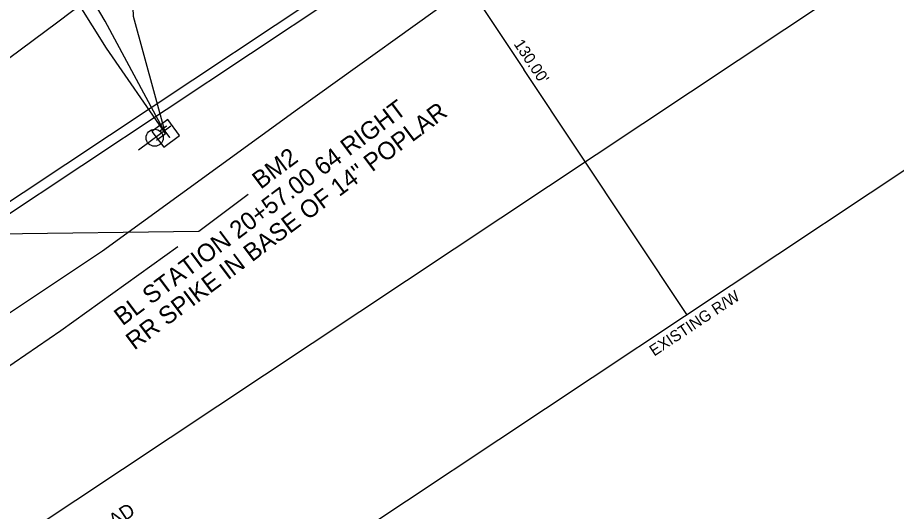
# Model space of a CAD drawing. Extents: x 2186615 to 2188822, y 629899 to 631820.
# Drawn here: x 2188055 to 2188303.7, y 630886.3 to 631026.2 of the extents above; entities that cross this region are included whole.
import ezdxf

# ---------------------------------------------------------------- set-up
doc = ezdxf.new("R2010")
doc.units = 0
for name, color, linetype in [('CTL Vertical Benchmark Leader', 7, 'Continuous'), ('CTL Vertical Benchmark Text', 7, 'Continuous'), ('Exist Railroads Standard Gauge', 7, 'Continuous'), ('Exist Railroads Standard Gauge Text', 7, 'Continuous'), ('Exist Right of Way Line', 7, 'Continuous'), ('Exist Right of Way Line Text', 7, 'Continuous'), ('Exist Right of Way Width CELL', 7, 'Continuous'), ('Exist Utilities Telephone Pedestal CELL', 7, 'Continuous'), ('Exist Utilities Telephone Pole CELL', 7, 'Continuous'), ('Exist Utilities Telephone UG Cable SUE LOS C', 7, 'Continuous'), ('Exist Vegetation Woods Line', 7, 'Continuous'), ('Scratch_Level_1', 7, 'Continuous')]:
    doc.layers.add(name, color=color, linetype=linetype)

msp = doc.modelspace()

# ---------------------------------------------------------------- linework, layer by layer
at = {"layer": 'CTL Vertical Benchmark Leader'}
msp.add_lwpolyline([(2187992.04, 630964.19), (2188106.31, 630965.69), (2188120.25, 630976.14)], dxfattribs=at)
at = {"layer": 'Exist Railroads Standard Gauge'}
msp.add_line((2187893.71, 630771.38), (2188414.52, 631117.54), dxfattribs=at)
at = {"layer": 'Exist Right of Way Line'}
for p, q in [((2187850.54, 630836.34), (2188624.63, 631350.85)), ((2187922.5, 630728.08), (2188696.59, 631242.58)), ((2187850.54, 630836.34), (2188371.34, 631182.5)), ((2187850.54, 630836.34), (2188371.34, 631182.5))]:
    msp.add_line(p, q, dxfattribs=at)
at = {"layer": 'Exist Right of Way Width CELL'}
for p in [(2188172.46, 631050.31), (2188244.42, 630942.04)]:
    msp.add_line(p, (2188198.28, 631011.45), dxfattribs=at)
at = {"layer": 'Exist Utilities Telephone Pedestal CELL'}
msp.add_line((2188096.88, 630993.34), (2188096.88, 630993.34), dxfattribs=at)
msp.add_lwpolyline([(2188096.4, 630989.45), (2188100.88, 630992.81), (2188097.52, 630997.28), (2188093.04, 630993.92), (2188096.4, 630989.45)], dxfattribs=at)
at = {"layer": 'Exist Utilities Telephone Pole CELL'}
for p, q in [((2188089.27, 630988.7), (2188098.35, 630995.5)), ((2188093.81, 630992.11), (2188093.81, 630992.11))]:
    msp.add_line(p, q, dxfattribs=at)
msp.add_circle((2188093.81, 630992.11), 2.41, dxfattribs=at)
at = {"layer": 'Exist Utilities Telephone UG Cable SUE LOS C'}
for points in [[(2188096.88, 630993.34), (2188080.22, 631017.51), (2188064.37, 631042.87), (2188062.98, 631045.24), (2188062.65, 631047.71), (2188067.09, 631054.3), (2188068.63, 631056.84), (2188089.09, 631072.74), (2188116.44, 631092.81), (2188141.03, 631110.94), (2188178.22, 631138.01), (2188229.96, 631175.9), (2188269.4, 631205.59), (2188294.58, 631224.2), (2188340.11, 631258.2), (2188382.72, 631289.85), (2188432.93, 631327.36), (2188477.32, 631360.56), (2188524.82, 631398.08), (2188530.94, 631402.62)], [(2188094.37, 630991.41), (2188096.88, 630993.34), (2188087.79, 631026.43), (2188086.82, 631054.16), (2188087.06, 631058.84), (2188088.93, 631062.35), (2188093.27, 631066.84), (2188121.22, 631086.85), (2188145.88, 631105.9), (2188182.55, 631131.21), (2188212.13, 631152.41), (2188236.63, 631168.55), (2188279.23, 631192.06), (2188292.43, 631201.57), (2188302.49, 631212.36), (2188347.67, 631244.49), (2188388.98, 631278.39), (2188439.32, 631316.4), (2188482.92, 631349.33), (2188532.32, 631387.1), (2188539.16, 631391.7)], [(2188096.88, 630993.34), (2188079.83, 631025.19), (2188068.51, 631044.39), (2188061.79, 631053.43), (2188045.22, 631077.41), (2188041.6, 631082.29), (2188043.38, 631085.49), (2188063.96, 631101.13), (2188102.69, 631130.96), (2188125.87, 631148.05), (2188163, 631175.72), (2188217.3, 631215.55), (2188224.13, 631221.73), (2188223.64, 631224.04), (2188219.58, 631228.63), (2188214.19, 631233.71)]]:
    msp.add_lwpolyline(points, dxfattribs=at)
at = {"layer": 'Exist Vegetation Woods Line'}
for points in [[(2187900, 630901.47), (2187930.95, 630926.02), (2187966.57, 630951.75), (2187999.62, 630976.07), (2188035.07, 631001.76), (2188066.4, 631024.95), (2188104.74, 631054.06), (2188133.99, 631077.57), (2188163.27, 631099.35), (2188198, 631125.47), (2188236.07, 631154.15), (2188273.27, 631182), (2188303.14, 631206.11), (2188341.9, 631232.33), (2188374.15, 631253.71), (2188405.25, 631276.99)], [(2187912.42, 630863.47), (2187965.88, 630898.63), (2188006.08, 630921.31), (2188016.76, 630922.95), (2188041.27, 630935.01), (2188079.01, 630960.1), (2188134.21, 631000.22), (2188184.55, 631036.37), (2188240.85, 631074.86), (2188450.68, 631218.94)], [(2188336.81, 631162.74), (2188304.67, 631140.79), (2188253.49, 631107.84), (2188202.91, 631074.1), (2188139.41, 631031.67), (2188093.1, 631000.83), (2188032.1, 630960.3), (2187970.81, 630919.03), (2187899.6, 630870.56), (2187878.91, 630858.57), (2187866.57, 630849.5), (2187856.84, 630841.46), (2187846.68, 630832.19), (2187829.94, 630827.76), (2187807.52, 630819.83), (2187838.54, 630838.9), (2187846.29, 630845.15), (2187849.33, 630854.22), (2187863.66, 630870.01), (2187881.14, 630887.73), (2187900, 630901.47)], [(2188100.36, 630961.19), (2188067.24, 630937.46), (2188044.04, 630921.54), (2188015.4, 630902.33), (2187990.59, 630885.5), (2187967.82, 630864.96), (2187943.51, 630846.5), (2187926.23, 630833.19), (2187904.9, 630814.71), (2187898.54, 630808.83)]]:
    msp.add_lwpolyline(points, dxfattribs=at)
at = {"layer": 'Scratch_Level_1'}
msp.add_line((2187893.71, 630771.38), (2188667.8, 631285.88), dxfattribs=at)

# ---------------------------------------------------------------- texts
at = {"layer": 'CTL Vertical Benchmark Text'}
for s, p in [('BL STATION 20+57.00 64 RIGHT', (2188084.71, 630938.71)), ('RR SPIKE IN BASE OF 14" POPLAR', (2188088.05, 630931.83)), ('BM2       ', (2188123.81, 630977.39))]:
    msp.add_text(s, height=5, rotation=36.8593, dxfattribs=at).set_placement(p)
at = {"layer": 'Exist Railroads Standard Gauge Text'}
msp.add_text('SEABOARD COASTLINE RAILROAD', height=4, rotation=33.6101, dxfattribs=at).set_placement((2188013.4, 630835.63))
at = {"layer": 'Exist Right of Way Line Text'}
msp.add_text('EXISTING R/W', height=3.2, rotation=33.6101, dxfattribs=at).set_placement((2188235.17, 630930.13))
at = {"layer": 'Exist Right of Way Width CELL'}
msp.add_text("130.00'", height=3.2, rotation=303.6101, dxfattribs=at).set_placement((2188195.3, 631018.7))
at = {"layer": 'Exist Utilities Telephone Pedestal CELL'}
msp.add_text('T', height=3.42, rotation=36.8892, dxfattribs=at).set_placement((2188097.01, 630991.29))

doc.saveas('drawing.dxf')
